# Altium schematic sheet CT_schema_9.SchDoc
size 251 x 159 mm
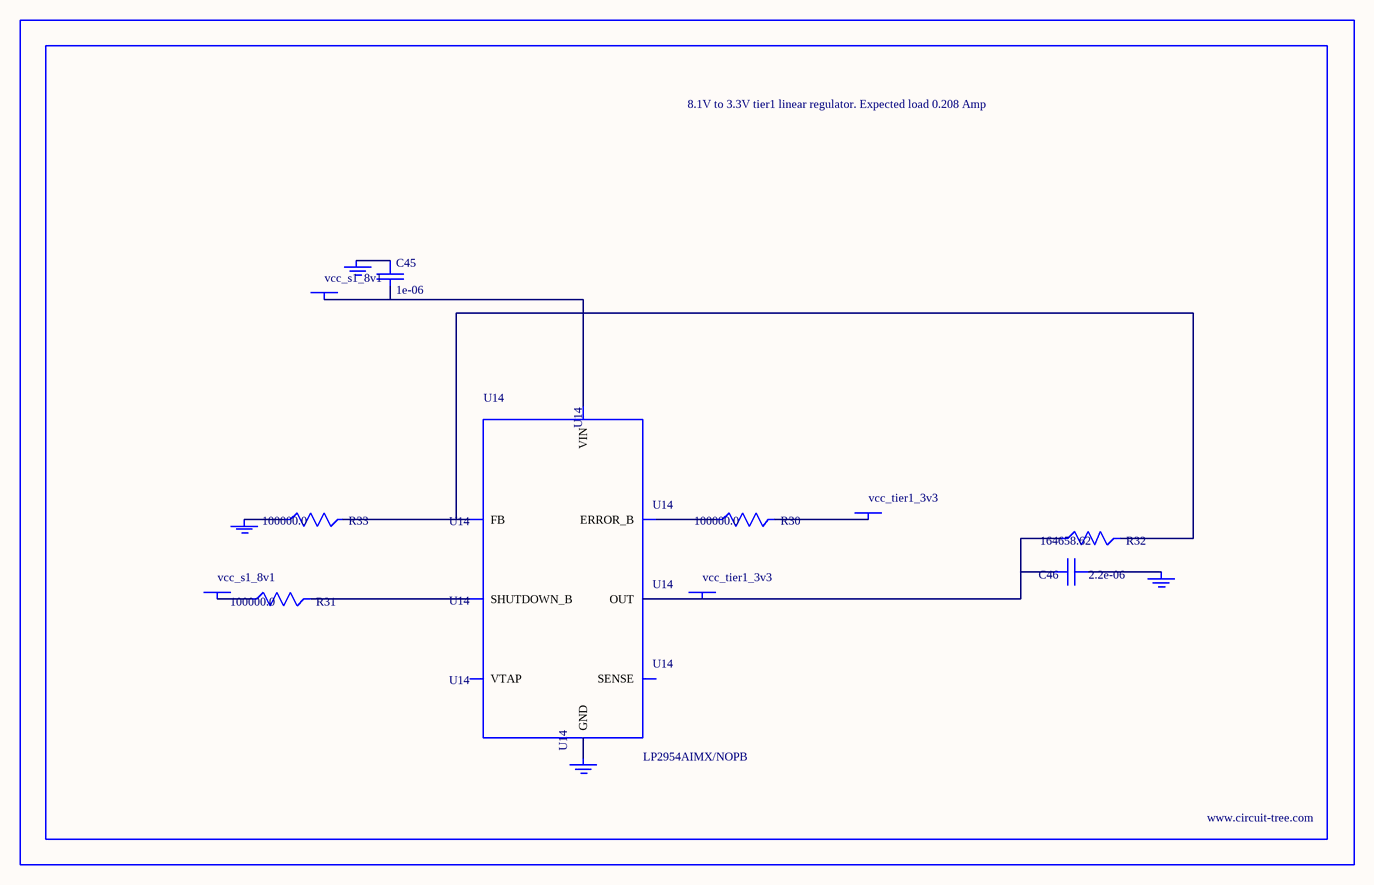
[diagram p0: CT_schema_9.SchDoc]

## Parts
BORDER8  (no value)
C45  1e-06  [EXV-9B]
C46  2.2e-06  [EXV-9B]
GND_INSTANCE_8_0  (no value)
GND_INSTANCE_8_1  (no value)
GND_INSTANCE_8_2  (no value)
GND_INSTANCE_8_3  (no value)
POWER_INSTANCE_8_0  vcc_s1_8v1
POWER_INSTANCE_8_1  vcc_tier1_3v3
POWER_INSTANCE_8_2  vcc_s1_8v1
POWER_INSTANCE_8_3  vcc_tier1_3v3
R30  100000.0  [R0603]
R31  100000.0  [R0603]
R32  164658.62  [R0603]
R33  100000.0  [R0603]
U14  LP2954AIMX/NOPB  [LP2954]

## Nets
NetC45_1: C45.1 GND_INSTANCE_8_2.0(GND)
NetC45_2: C45.2 POWER_INSTANCE_8_2.0(PWR) U14.8(VIN)
NetC46_1: C46.1 GND_INSTANCE_8_0.0(GND)
NetC46_2: C46.2 POWER_INSTANCE_8_3.0(PWR) R32.1 U14.1(OUT)
NetGND_INSTANCE_8_1_0: GND_INSTANCE_8_1.0(GND) R33.1
NetGND_INSTANCE_8_3_0: GND_INSTANCE_8_3.0(GND) U14.4(GND)
NetPOWER_INSTANCE_8_0_0: POWER_INSTANCE_8_0.0(PWR) R31.1
NetPOWER_INSTANCE_8_1_0: POWER_INSTANCE_8_1.0(PWR) R30.2
NetR30_1: R30.1 U14.5(ERROR_B)
NetR31_2: R31.2 U14.3(SHUTDOWN_B)
NetR32_2: R32.2 R33.2 U14.7(FB)

Not connected (* = marked no-connect by the designer): U14 2(SENSE) 6(VTAP)

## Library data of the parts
BORDER8 = BORDER_PAGE8
C45 = EDK105M050A9BAA
C46 = EDK225M050A9BAA
GND_INSTANCE_8_0-GND_INSTANCE_8_3 = GND
POWER_INSTANCE_8_0-POWER_INSTANCE_8_3 = PWR
R30 R31 R33 = RC0603JR-07100KL
R32 = R32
